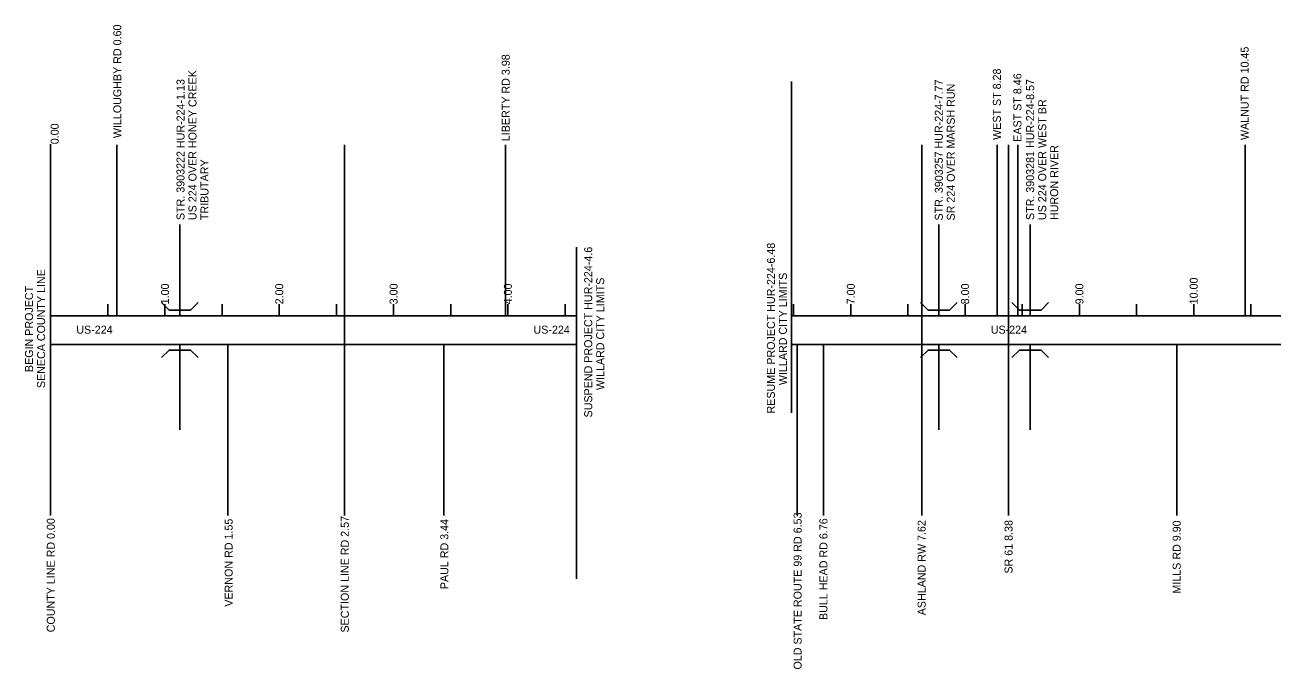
# Model space of a CAD drawing. Extents: x 20550.2 to 20593.9, y 6180.6 to 6241.4.
# Drawn here: x 20550.21 to 20572.06, y 6228.19 to 6239.47 of the extents above; entities that cross this region are included whole.
import ezdxf

# ---------------------------------------------------------------- set-up
doc = ezdxf.new("R2010")
doc.units = 0
for name, color, linetype in [('CM_Corridor_Range_Design', 7, 'Continuous'), ('DR_X_Culvert', 7, 'Continuous'), ('MD_X_Asphalt_Pavement', 7, 'Continuous'), ('PV_X_EOP', 7, 'Continuous'), ('RD_X_RR_1', 7, 'Continuous'), ('SH_Data', 7, 'Continuous'), ('SH_Text', 7, 'Continuous')]:
    doc.layers.add(name, color=color, linetype=linetype)

msp = doc.modelspace()

# ---------------------------------------------------------------- linework, layer by layer
at = {"layer": 'CM_Corridor_Range_Design'}
for p, q in [((20563.636, 6232.672), (20563.636, 6238.478)), ((20550.662, 6237.377), (20550.662, 6230.878)), ((20559.872, 6235.575), (20559.872, 6229.769))]:
    msp.add_line(p, q, dxfattribs=at)
at = {"layer": 'DR_X_Culvert'}
for p, q in [((20552.925, 6235.972), (20552.925, 6234.474)), ((20566.219, 6235.972), (20566.219, 6234.474)), ((20567.821, 6235.972), (20567.821, 6234.474)), ((20552.925, 6234.374), (20552.925, 6234.474)), ((20566.219, 6234.374), (20566.219, 6234.474)), ((20567.821, 6234.374), (20567.821, 6234.474)), ((20550.662, 6234.374), (20552.925, 6234.374)), ((20552.925, 6233.873), (20552.925, 6233.773)), ((20552.925, 6233.873), (20552.925, 6232.376)), ((20566.219, 6233.873), (20566.219, 6233.773)), ((20566.219, 6233.873), (20566.219, 6232.376)), ((20567.821, 6233.873), (20567.821, 6233.773)), ((20567.821, 6233.873), (20567.821, 6232.376))]:
    msp.add_line(p, q, dxfattribs=at)
for points in [[(20552.604, 6234.607), (20552.737, 6234.474), (20553.113, 6234.474), (20553.245, 6234.607)], [(20565.899, 6234.607), (20566.031, 6234.474), (20566.407, 6234.474), (20566.54, 6234.607)], [(20567.5, 6234.607), (20567.633, 6234.474), (20568.009, 6234.474), (20568.141, 6234.607)], [(20552.604, 6233.641), (20552.737, 6233.773), (20553.113, 6233.773), (20553.245, 6233.641)], [(20565.899, 6233.641), (20566.031, 6233.773), (20566.407, 6233.773), (20566.54, 6233.641)], [(20567.5, 6233.641), (20567.633, 6233.773), (20568.009, 6233.773), (20568.141, 6233.641)]]:
    msp.add_lwpolyline(points, dxfattribs=at)
at = {"layer": 'MD_X_Asphalt_Pavement'}
for p, q in [((20551.824, 6237.369), (20551.824, 6234.374)), ((20555.808, 6237.369), (20555.808, 6230.878)), ((20558.631, 6237.369), (20558.631, 6234.374)), ((20567.24, 6237.369), (20567.24, 6234.374)), ((20567.441, 6237.369), (20567.441, 6230.878)), ((20567.601, 6237.369), (20567.601, 6234.374)), ((20571.585, 6237.369), (20571.585, 6234.374)), ((20550.662, 6233.873), (20550.662, 6230.878)), ((20553.766, 6233.873), (20553.766, 6230.878)), ((20557.55, 6233.873), (20557.55, 6230.878)), ((20563.737, 6233.873), (20563.737, 6230.878)), ((20564.197, 6233.873), (20564.197, 6230.878)), ((20570.386, 6233.873), (20570.386, 6230.878))]:
    msp.add_line(p, q, dxfattribs=at)
at = {"layer": 'PV_X_EOP'}
for p, q in [((20550.662, 6234.374), (20559.872, 6234.374)), ((20563.636, 6234.374), (20587.943, 6234.374)), ((20550.662, 6233.873), (20550.662, 6233.881)), ((20550.662, 6233.873), (20559.872, 6233.873)), ((20563.636, 6233.873), (20587.943, 6233.873))]:
    msp.add_line(p, q, dxfattribs=at)
at = {"layer": 'RD_X_RR_1'}
msp.add_line((20565.919, 6237.369), (20565.919, 6230.878), dxfattribs=at)
at = {"layer": 'SH_Data'}
for p, q in [((20551.664, 6234.374), (20551.664, 6234.574)), ((20552.665, 6234.374), (20552.665, 6234.574)), ((20553.666, 6234.374), (20553.666, 6234.574)), ((20554.667, 6234.374), (20554.667, 6234.574)), ((20555.668, 6234.374), (20555.668, 6234.574)), ((20556.669, 6234.374), (20556.669, 6234.574)), ((20557.67, 6234.374), (20557.67, 6234.574)), ((20558.671, 6234.374), (20558.671, 6234.574)), ((20559.672, 6234.374), (20559.672, 6234.574)), ((20563.676, 6234.374), (20563.676, 6234.574)), ((20564.678, 6234.374), (20564.678, 6234.574)), ((20565.679, 6234.374), (20565.679, 6234.574)), ((20566.68, 6234.374), (20566.68, 6234.574)), ((20567.681, 6234.374), (20567.681, 6234.574)), ((20568.682, 6234.374), (20568.682, 6234.574)), ((20569.683, 6234.374), (20569.683, 6234.574)), ((20570.684, 6234.374), (20570.684, 6234.574)), ((20571.685, 6234.374), (20571.685, 6234.574))]:
    msp.add_line(p, q, dxfattribs=at)

# ---------------------------------------------------------------- texts
at = {"layer": 'SH_Text'}
for s, height, p in [('WILLOUGHBY RD 0.60', 0.14015, (20551.9, 6237.484)), ('WALNUT RD 10.45', 0.14015, (20571.646, 6237.451)), ('LIBERTY RD 3.98', 0.14015, (20558.703, 6237.432)), ('US 224 OVER HONEY CREEK', 0.14015, (20553.217, 6236.049)), ('WEST ST 8.28', 0.14015, (20567.306, 6237.453)), ('EAST ST 8.46', 0.14015, (20567.666, 6237.421)), ('STR. 3903222 HUR-224-1.13', 0.14015, (20553.007, 6236.049)), ('STR. 3903257 HUR-224-7.77', 0.14015, (20566.289, 6236.042)), ('SR 224 OVER MARSH RUN', 0.14015, (20566.499, 6236.042)), ('STR. 3903281 HUR-224-8.57', 0.14015, (20567.889, 6236.05)), ('US 224 OVER WEST BR', 0.14015, (20568.1, 6236.05)), ('0.00', 0.1402, (20550.803, 6237.377)), ('HURON RIVER', 0.14015, (20568.31, 6236.05)), ('TRIBUTARY', 0.1402, (20553.427, 6236.049)), ('SUSPEND PROJECT HUR-224-4.6', 0.14015, (20560.148, 6232.593)), ('RESUME PROJECT HUR-224-6.48', 0.14015, (20563.348, 6232.663)), ('SENECA COUNTY LINE', 0.14015, (20550.565, 6233.107)), ('WILLARD CITY LIMITS', 0.14015, (20563.558, 6233.159)), ('BEGIN PROJECT', 0.14015, (20550.354, 6233.388)), ('1.00', 0.1402, (20552.735, 6234.574)), ('2.00', 0.1402, (20554.737, 6234.574)), ('3.00', 0.1402, (20556.739, 6234.574)), ('4.00', 0.1402, (20558.741, 6234.574)), ('WILLARD CITY LIMITS', 0.14015, (20560.358, 6233.073)), ('7.00', 0.1402, (20564.748, 6234.574)), ('8.00', 0.1402, (20566.75, 6234.574)), ('9.00', 0.1402, (20568.752, 6234.574)), ('10.00', 0.1402, (20570.754, 6234.574)), ('COUNTY LINE RD 0.00', 0.14015, (20550.735, 6228.831)), ('VERNON RD 1.55', 0.14015, (20553.85, 6229.279)), ('SECTION LINE RD 2.57', 0.14015, (20555.885, 6228.827)), ('PAUL RD 3.44', 0.14015, (20557.628, 6229.586)), ('OLD STATE ROUTE 99 RD 6.53', 0.14015, (20563.816, 6228.179)), ('BULL HEAD RD 6.76', 0.14015, (20564.268, 6229.046)), ('ASHLAND RW 7.62', 0.14015, (20565.988, 6229.129)), ('SR 61 8.38', 0.1402, (20567.511, 6229.859)), ('MILLS RD 9.90', 0.14015, (20570.455, 6229.509))]:
    msp.add_text(s, height=height, rotation=90, dxfattribs=at).set_placement(p)
for p in [(20551.112, 6234.06), (20559.12, 6234.06), (20567.129, 6234.06)]:
    msp.add_text('US-224', height=0.1402, dxfattribs=at).set_placement(p)

doc.saveas('drawing.dxf')
